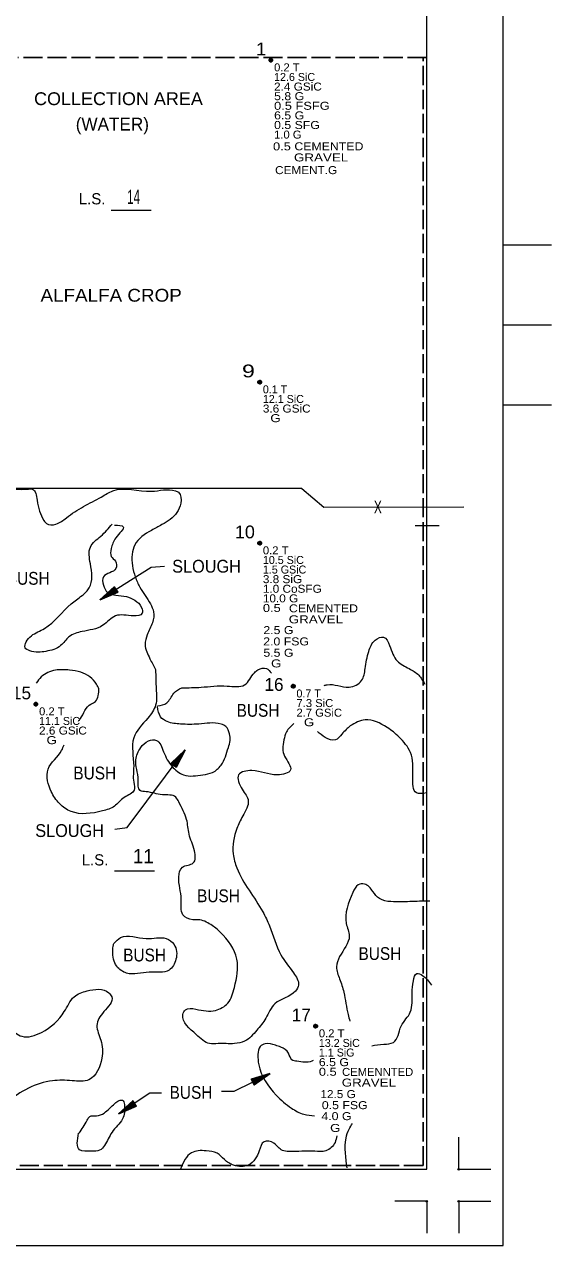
# Model space of a CAD drawing. Extents: x -496 to 480, y -450 to 700.
# Drawn here: x 151 to 480, y -450 to 313 of the extents above; entities that cross this region are included whole.
import ezdxf
from ezdxf.enums import TextEntityAlignment as Align

# ---------------------------------------------------------------- set-up
doc = ezdxf.new("R2010")
doc.units = 0
doc.header["$LTSCALE"] = 2
doc.header["$PDMODE"] = 32
doc.header["$PDSIZE"] = 1
doc.linetypes.add('LONG_DASHED', pattern=[7.5, 6, -1.5])
for name, color, linetype, lineweight in [('1', 7, 'Continuous', 13), ('2', 7, 'Continuous', 35), ('3', 7, 'Continuous', 13), ('4', 7, 'Continuous', 25)]:
    doc.layers.add(name, color=color, linetype=linetype, lineweight=lineweight)

msp = doc.modelspace()

# ---------------------------------------------------------------- linework, layer by layer
at = {"layer": '1'}
for p, q in [((205.122, 196.887), (230.122, 196.887)), ((480.331, 174.973), (449.983, 174.973)), ((480.331, 124.973), (449.983, 124.973)), ((480.331, 74.973), (449.983, 74.973)), ((394.983, -0.027), (409.983, -0.027)), ((207.114, -215.907), (232.114, -215.907)), ((422.281, -402.333), (422.281, -382.333)), ((-402.391, -402.333), (402.281, -402.333)), ((422.281, -402.333), (442.281, -402.333)), ((402.281, -422.333), (382.281, -422.333)), ((402.281, -422.333), (402.281, -442.333)), ((422.281, -422.333), (422.281, -442.333)), ((422.281, -422.333), (442.281, -422.333)), ((-450.017, -450.027), (449.983, -450.027))]:
    msp.add_line(p, q, dxfattribs=at)
for points in [[(449.983, -450.027), (449.983, 399.973), (449.983, 699.973), (-450.017, 699.973), (-450.017, 49.973), (-450.017, -450.027)], [(402.281, -402.333), (402.281, 402.339), (-402.391, 402.339)]]:
    msp.add_lwpolyline(points, dxfattribs=at)
for p in [(422.281, -402.333), (402.281, -422.333), (422.281, -422.333)]:
    msp.add_point(p, dxfattribs=at)
at = {"layer": '2', "linetype": 'LONG_DASHED', "lineweight": 25}
for p, q in [((402.281, 292.339), (146.811, 292.339)), ((400, -400), (400, 292.339)), ((400, -400), (-292.391, -400))]:
    msp.add_line(p, q, dxfattribs=at)
at = {"layer": '2'}
for centre in [(304.915, 290.604), (297.921, 89.429), (297.921, -11.159), (318.901, -100.57), (158.055, -111.747), (332.888, -312.922)]:
    msp.add_circle(centre, 1, dxfattribs=at)
for points in [[(304.904, 291.491), (305.634, 291.087), (305.786, 290.239), (305.101, 289.711), (304.292, 289.941), (304.005, 290.699), (304.253, 291.261), (304.826, 291.429), (305.5, 290.935), (305.483, 290.194), (304.966, 289.935), (304.444, 290.104), (304.219, 290.75), (304.803, 291.216), (305.241, 290.682), (305.202, 290.199), (304.573, 290.334), (304.719, 290.969), (305.011, 290.418)], [(297.911, 90.316), (298.641, 89.911), (298.793, 89.063), (298.107, 88.535), (297.299, 88.766), (297.012, 89.524), (297.259, 90.085), (297.832, 90.254), (298.506, 89.76), (298.489, 89.018), (297.973, 88.76), (297.45, 88.928), (297.226, 89.574), (297.81, 90.041), (298.248, 89.507), (298.208, 89.024), (297.579, 89.159), (297.725, 89.793), (298.018, 89.243)], [(297.911, -10.272), (298.641, -10.676), (298.793, -11.524), (298.107, -12.052), (297.299, -11.822), (297.012, -11.064), (297.259, -10.502), (297.832, -10.334), (298.506, -10.828), (298.489, -11.569), (297.973, -11.828), (297.45, -11.659), (297.226, -11.013), (297.81, -10.547), (298.248, -11.081), (298.208, -11.564), (297.579, -11.429), (297.725, -10.794), (298.018, -11.345)], [(318.891, -99.683), (319.621, -100.088), (319.773, -100.936), (319.087, -101.464), (318.279, -101.233), (317.992, -100.475), (318.239, -99.914), (318.812, -99.745), (319.486, -100.239), (319.469, -100.981), (318.953, -101.239), (318.43, -101.071), (318.206, -100.425), (318.79, -99.958), (319.228, -100.492), (319.188, -100.975), (318.559, -100.84), (318.705, -100.206), (318.998, -100.756)], [(158.044, -110.86), (158.775, -111.264), (158.926, -112.112), (158.241, -112.64), (157.432, -112.41), (157.146, -111.652), (157.393, -111.09), (157.966, -110.921), (158.64, -111.416), (158.623, -112.157), (158.106, -112.415), (157.584, -112.247), (157.359, -111.601), (157.943, -111.135), (158.381, -111.668), (158.342, -112.152), (157.713, -112.017), (157.859, -111.382), (158.151, -111.932)], [(332.877, -312.035), (333.608, -312.439), (333.759, -313.287), (333.074, -313.815), (332.265, -313.585), (331.979, -312.827), (332.226, -312.265), (332.799, -312.097), (333.473, -312.591), (333.456, -313.332), (332.939, -313.591), (332.417, -313.422), (332.192, -312.776), (332.776, -312.31), (333.214, -312.844), (333.175, -313.327), (332.546, -313.192), (332.692, -312.557), (332.984, -313.108)]]:
    msp.add_spline(points, degree=3, dxfattribs=at)
at = {"layer": '3'}
msp.add_line((324.354, 23.005), (-397.391, 23.005), dxfattribs=at)
msp.add_lwpolyline([(324.354, 23.005), (338.092, 11.316), (425.468, 11.604)], dxfattribs=at)
for points in [[(102.089, 19.626), (103.394, 21.581), (152.651, 22.558), (155.913, 22.558), (158.849, 15.716), (163.09, 3.009), (164.721, 1.054), (170.592, 0.728), (177.117, 4.638), (187.881, 11.806), (198.972, 17.671), (206.149, 21.581), (230.288, 21.255), (245.293, 21.581), (247.251, 20.603), (248.555, 13.761), (242.031, 3.66), (236.812, 0.402), (230.288, -3.182), (219.849, -12.305), (218.218, -18.17), (220.176, -32.181), (223.111, -38.697), (229.636, -49.124), (231.593, -54.011), (230.94, -60.853), (227.678, -68.347), (226.373, -74.538), (229.309, -83.335), (232.898, -90.178)], [(207.127, 0.076), (212.673, -0.901), (208.106, -7.744), (205.17, -14.586), (205.17, -19.473), (207.78, -22.406), (208.106, -26.967), (200.277, -32.181), (200.277, -37.394), (202.887, -41.955), (208.106, -43.585), (214.63, -44.562), (219.849, -46.843), (224.09, -51.404), (224.416, -54.988), (219.197, -56.618), (207.78, -56.618), (199.951, -62.482), (186.903, -66.392), (178.748, -69.651), (173.528, -75.19), (164.395, -78.774), (154.282, -78.448), (151.346, -76.493), (151.999, -72.909), (155.261, -68.999), (163.416, -64.437), (180.052, -49.124), (186.903, -43.91), (191.47, -39.023), (192.122, -24.035), (192.122, -13.608), (198.646, -6.766), (205.823, 0.728)], [(338.162, -100.06), (340.038, -99.599), (353.797, -101.085), (361.606, -96.999), (363.837, -89.571), (366.068, -78.799), (370.159, -71.742), (375.365, -69.885), (379.083, -75.085), (383.918, -84.742), (391.355, -89.571), (397.304, -93.656), (401.023, -99.228)], [(184.663, -122.476), (185.924, -120.806), (192.448, -111.682), (195.384, -110.053), (197.015, -106.469), (197.341, -102.233), (196.036, -99.301), (186.25, -91.807), (179.074, -90.504), (170.266, -90.504), (161.459, -94.739), (158.269, -98.623)], [(232.898, -90.178), (233.224, -102.233), (232.898, -112.334), (228.004, -120.48), (219.197, -132.861), (219.197, -150.456), (219.197, -160.556), (219.523, -165.444), (213.325, -170.005), (207.127, -175.544), (199.625, -178.477), (180.052, -178.803), (172.876, -173.915), (167.657, -166.421), (165.373, -159.579), (165.699, -152.411), (174.181, -140.681), (175.678, -137.07)], [(249.247, -101.556), (261.337, -101.179), (277.583, -100.424), (288.54, -99.669), (294.585, -92.122), (296.852, -90.235), (302.141, -89.48), (305.273, -92.352)], [(234.135, -112.877), (239.802, -110.99), (244.336, -104.952), (249.247, -101.556)], [(319.303, -123.874), (314.609, -129.105), (313.098, -134.01), (312.342, -139.671), (313.476, -144.2), (317.254, -152.879), (308.942, -155.898), (293.074, -153.257), (284.762, -155.898), (287.029, -164.955), (290.807, -172.125), (287.407, -181.56), (283.628, -189.485), (281.362, -205.335), (283.628, -214.014), (299.874, -241.563), (304.03, -250.242), (311.209, -268.356), (319.143, -279.678), (322.165, -287.225), (320.276, -290.999), (307.431, -298.924), (301.763, -307.981), (296.096, -315.528), (288.54, -322.321), (282.117, -323.831), (271.916, -323.831), (266.627, -323.831), (258.315, -318.17), (250.003, -305.717), (251.514, -302.698), (257.937, -302.32), (270.405, -303.075), (277.961, -298.546), (282.117, -288.735), (283.628, -270.998), (273.427, -254.393), (267.382, -249.488), (259.448, -246.469), (256.048, -246.469), (250.003, -243.45), (248.87, -233.638), (247.358, -219.675), (249.625, -213.637), (256.426, -210.995), (257.181, -203.448), (253.781, -192.881), (252.27, -183.824), (247.358, -172.88), (245.469, -169.861), (237.157, -168.352), (226.956, -166.465), (223.178, -165.71), (222.045, -159.295), (220.534, -146.464), (223.556, -138.916), (228.468, -134.765), (233.379, -134.388), (237.913, -141.558), (243.202, -150.615), (250.381, -155.898), (262.471, -155.898), (268.516, -154.389), (273.805, -149.86), (278.339, -138.916), (279.472, -134.388), (279.095, -130.237), (276.828, -125.708), (273.805, -124.199), (259.826, -124.199), (248.492, -124.199), (240.18, -122.689), (236.024, -119.67), (234.135, -113.255)], [(402.138, -167.199), (395.817, -167.199), (393.586, -157.17), (392.098, -141.942), (385.033, -132.285), (377.596, -126.342), (363.837, -121.513), (354.541, -125.228)], [(354.541, -125.228), (349.335, -130.427), (345.244, -134.142), (338.923, -132.656), (333.952, -128.787)], [(404.151, -234.77), (391.683, -235.147), (379.971, -235.147), (372.792, -233.26), (368.636, -228.732), (363.347, -224.203), (359.569, -224.581), (356.169, -229.487), (352.013, -248.733), (353.902, -256.658), (347.857, -269.488), (345.968, -275.904), (347.857, -283.451), (350.501, -291.754), (353.146, -305.717), (354.268, -309.871)], [(206.706, -261.289), (211.03, -257.587), (227.091, -258.204), (239.445, -258.204), (244.387, -261.906), (245.623, -271.161), (241.299, -277.948), (228.944, -279.182), (214.736, -279.799), (208.559, -275.48), (206.088, -266.225), (206.088, -263.989)], [(206.088, -263.989), (206.482, -262.172), (206.706, -261.289)], [(367.913, -325.201), (375.437, -324.208), (381.482, -323.076), (386.394, -312.887), (392.061, -304.207), (393.194, -292.131), (393.95, -284.584), (396.217, -280.055), (399.617, -281.187), (405.284, -287.225)], [(138.872, -311.849), (141.226, -313.735), (149.257, -319.288), (161.611, -316.82), (175.819, -303.863), (181.996, -294.608), (190.027, -290.906), (203.617, -292.14), (205.47, -294.608), (200.528, -303.863), (196.204, -312.501), (198.675, -321.756), (199.293, -332.863), (191.262, -346.437), (180.761, -347.054), (168.406, -347.054), (139.991, -360.628), (125.783, -373.586), (112.811, -385.309), (107.251, -396.415), (65.245, -397.032), (32.506, -397.032), (24.475, -389.011), (17.68, -382.224), (12.12, -386.543), (-15.677, -391.479), (-29.268, -397.032), (-48.417, -396.415), (-83.628, -396.415)], [(331.448, -334.439), (330.463, -334.882), (321.17, -334.882), (318.072, -333.93), (315.927, -329.884), (311.161, -326.075), (307.825, -324.885), (301.39, -323.933), (298.292, -325.599), (296.862, -330.598), (297.339, -337.025), (308.301, -356.067), (317.833, -364.16), (325.459, -367.968), (332.153, -369.003)], [(185.049, -379.848), (190.114, -371.709), (191.766, -369.399), (195.95, -368.959), (200.685, -367.199), (207.402, -361.26), (210.155, -359.39), (212.137, -359.17), (213.348, -361.92), (212.137, -370.939), (205.64, -379.188), (201.015, -387.437), (197.932, -390.516), (192.757, -391.066), (185.379, -390.186), (184.718, -379.738)], [(352.626, -401.53), (351.911, -382.964), (353.817, -377.252), (355.843, -373.842)], [(346.106, -381.405), (345, -385.583), (339.281, -390.819), (332.37, -391.057), (316.165, -391.295), (312.114, -390.581), (306.871, -386.059), (300.675, -385.107), (297.577, -390.819), (295.194, -395.818), (290.667, -399.864), (286.615, -400.578), (281.611, -399.864), (275.892, -396.294), (271.364, -392.247), (264.453, -390.819), (259.449, -390.819), (255.397, -392.009), (248.487, -402.245)]]:
    msp.add_spline(points, degree=3, dxfattribs=at)
at = {"layer": '4', "lineweight": 13}
for points in [[(238.547, -25.67), (230.042, -26.323), (197.984, -46.582)], [(207.391, -189.864), (215.101, -188.731), (251.382, -140.262)], [(273.982, -353.542), (282.059, -353.542), (304.406, -342.516)], [(236.557, -354.887), (229.288, -354.887), (209.633, -367.796)]]:
    msp.add_lwpolyline(points, dxfattribs=at)
at = {"layer": '4'}
for points in [[(197.984, -46.582), (209.196, -41.862), (207.06, -38.48)], [(251.382, -140.262), (242.59, -148.67), (245.792, -151.067)], [(304.406, -342.516), (292.759, -346.033), (294.529, -349.62)], [(209.633, -367.796), (220.761, -362.88), (218.566, -359.536)]]:
    msp.add_lwpolyline(points, close=True, dxfattribs=at)
for points in [[(209.05, -41.814), (198.469, -46.276), (207.01, -38.706), (208.92, -41.691), (199.092, -45.882), (206.937, -38.955), (208.695, -41.655), (199.75, -45.467), (206.889, -39.243), (208.47, -41.542), (200.509, -45.012), (206.791, -39.535), (208.17, -41.475), (201.418, -44.465), (206.765, -39.858), (207.849, -41.37), (202.396, -43.871), (206.701, -40.282), (207.504, -41.309), (203.492, -43.255), (206.548, -40.686), (207.091, -41.263), (204.742, -42.441), (206.415, -41.203)], [(242.744, -148.663), (251.038, -140.721), (245.758, -150.838), (242.909, -148.731), (250.596, -141.31), (245.738, -150.58), (243.132, -148.685), (250.13, -141.933), (245.68, -150.294), (243.382, -148.71), (249.583, -142.629), (245.667, -149.986), (243.687, -148.666), (248.929, -143.464), (245.576, -149.675), (244.024, -148.649), (248.227, -144.368), (245.484, -149.256), (244.369, -148.583), (247.422, -145.334), (245.484, -148.825), (244.77, -148.479), (246.545, -146.541), (245.424, -148.294)], [(292.9, -346.095), (303.891, -342.77), (294.603, -349.4), (293.016, -346.232), (303.23, -343.096), (294.701, -349.161), (293.236, -346.291), (302.532, -343.44), (294.779, -348.879), (293.448, -346.427), (301.73, -343.813), (294.907, -348.599), (293.739, -346.526), (300.768, -344.261), (294.967, -348.28), (294.047, -346.663), (299.733, -344.749), (295.075, -347.866), (294.384, -346.76), (298.578, -345.246), (295.269, -347.48), (294.79, -346.849), (297.25, -345.925), (295.456, -346.98)], [(220.615, -362.835), (210.113, -367.481), (218.52, -359.763), (220.482, -362.713), (210.729, -367.077), (218.451, -360.013), (220.257, -362.682), (211.38, -366.65), (218.408, -360.302), (220.03, -362.573), (212.13, -366.181), (218.315, -360.596), (219.728, -362.51), (213.03, -365.619), (218.295, -360.919), (219.406, -362.412), (213.998, -365.008), (218.239, -361.344), (219.059, -362.357), (215.083, -364.373), (218.093, -361.75), (218.646, -362.318), (216.318, -363.537), (217.969, -362.27)]]:
    msp.add_lwpolyline(points, dxfattribs=at)

# ---------------------------------------------------------------- texts
at = {"layer": '1'}
for s, height, p in [('L.S.', 7, (193.216, 200.511)), ('L.S.', 7, (195.033, -212.53)), ('11', 8.89, (225.202, -211.189))]:
    msp.add_text(s, height=height, dxfattribs=at).set_placement(p, align=Align.CENTER)
at = {"layer": '1', "width": 0.6}
msp.add_text('14', height=8.89, dxfattribs=at).set_placement((219.146, 200.791), align=Align.CENTER)
at = {"layer": '2'}
for s, width, p in [('  1', 1.05, (301.915, 293.604)), ('  9', 1.35, (294.921, 92.429)), (' 10', 1.05, (294.921, -8.159))]:
    msp.add_text(s, height=8, dxfattribs=dict(at, width=width)).set_placement(p, align=Align.RIGHT)
for s, width, p in [('0.2 T      ', 1.05, (306.915, 283.604)), ('2.4 GSiC   ', 1.1, (306.915, 271.604)), ('5.8 G      ', 1.15, (306.915, 265.604)), ('0.5 FSFG   ', 1.2, (306.915, 259.604)), ('0.5 SFG    ', 1.15, (306.915, 247.604)), ('6.5 G      ', 1.15, (306.915, 253.604)), ('1.0 G      ', 1.05, (306.915, 241.604)), ('0.5        ', 1.2, (306.26, 234.235)), ('CEMENTED   ', 1.15, (319.613, 234.279)), ('GRAVEL     ', 1.25, (319.359, 227.337)), ('CEMENT.G   ', 1.1, (307.533, 219.404)), ('3.6 GSiC   ', 1.1, (299.921, 70.429)), ('  G        ', 1.25, (299.921, 64.429)), ('0.2 T      ', 1.05, (299.921, -18.159)), ('3.8 SiG    ', 1.1, (299.921, -36.159)), ('1.0 CoSFG  ', 1.1, (299.921, -42.159)), ('10.0 G     ', 1.1, (299.921, -48.159)), ('0.5        ', 1.2, (299.921, -54.159)), ('CEMENTED   ', 1.15, (316.215, -54.403)), ('GRAVEL     ', 1.25, (316.094, -61.274)), ('2.5 G      ', 1.15, (300.224, -67.984)), ('2.0 FSG    ', 1.15, (300.125, -75.057)), ('5.5 G      ', 1.15, (300.224, -82.137)), ('  G        ', 1.25, (300.378, -88.794)), ('0.2 T      ', 1.05, (160.055, -118.747)), ('2.7 GSiC   ', 1.05, (320.901, -119.57)), ('7.3 SiC    ', 1.05, (320.901, -113.57)), ('  G        ', 1.25, (320.901, -125.57)), ('2.6 GSiC   ', 1.1, (160.055, -130.747)), ('  G        ', 1.25, (160.055, -136.747)), ('0.2 T      ', 1.05, (334.888, -319.922)), ('6.5 G      ', 1.15, (334.888, -337.922)), ('0.5        ', 1.2, (334.888, -343.922)), ('CEMENNTED  ', 1.05, (349.411, -344.032)), ('GRAVEL     ', 1.25, (349.193, -350.686)), ('12.5 G     ', 1.1, (335.871, -357.886)), ('0.5 FSG    ', 1.15, (336.766, -364.797)), ('4.0 G      ', 1.15, (336.485, -371.658)), ('  G        ', 1.25, (337.272, -379.037))]:
    msp.add_text(s, height=5, dxfattribs=dict(at, width=width)).set_placement(p)
for s, p in [('12.6 SiC   ', (306.915, 277.604)), ('0.1 T      ', (299.921, 82.429)), ('12.1 SiC   ', (299.921, 76.429)), ('10.5 SiC   ', (299.921, -24.159)), ('1.5 GSiC   ', (299.921, -30.159)), ('0.7 T      ', (320.901, -107.57)), ('11.1 SiC   ', (160.055, -124.747)), ('13.2 SiC   ', (334.888, -325.922)), ('1.1 SiG    ', (334.888, -331.922))]:
    msp.add_text(s, height=5, dxfattribs=at).set_placement(p)
for s, p in [(' 16', (312.828, -103.456)), (' 15', (155.055, -108.747)), (' 17', (329.888, -309.922))]:
    msp.add_text(s, height=8, dxfattribs=at).set_placement(p, align=Align.RIGHT)
at = {"layer": '3', "width": 0.7}
msp.add_text('X', height=8, dxfattribs=at).set_placement((371.774, 7.398), align=Align.CENTER)
at = {"layer": '4'}
for s, width, p in [('COLLECTION AREA', 1.05, (209.672, 262.528)), ('ALFALFA CROP', 1.1, (205.109, 139.716)), ('SLOUGH', 0.95, (264.717, -29.591)), ('BUSH', 0.9, (153.299, -37.149)), ('BUSH', 0.9, (296.894, -119.622)), ('BUSH', 0.9, (194.856, -158.78)), ('SLOUGH', 0.95, (179.158, -194.75)), ('BUSH', 0.9, (272.19, -235.488)), ('BUSH', 0.9, (226.005, -272.5)), ('BUSH', 0.9, (373.049, -271.592)), ('BUSH', 0.9, (255.005, -358.327))]:
    msp.add_text(s, height=8, dxfattribs=dict(at, width=width)).set_placement(p, align=Align.CENTER)
msp.add_text('(WATER)', height=8, dxfattribs=at).set_placement((205.859, 246.659), align=Align.CENTER)

doc.saveas('drawing.dxf')
